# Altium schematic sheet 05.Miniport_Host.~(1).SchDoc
size A4; CheckedBy: <审核日期>; Author: 黄雄波; CompanyName: 广州周立功单片机科技有限公司; DocumentNumber: 5; SheetNumber: 5; SheetTotal: 7; PageSetup: Record=PageOptions¦CenterHorizontal=True¦CenterVertical=True¦PrintScale=1.00¦XCorrection=1.00¦YCorrection=1.00¦PrintKind=0¦BorderSize=5000000¦LeftOffset=0¦BottomOffset=0¦Orientation=2¦PaperLength=1000¦PaperWidth=1000¦Scale=100¦PaperSource=7¦PrintQuality=600¦MediaType=1¦DitherType=10¦PaperKind=A4¦PrintScaleMode=1; DesignDate: 2016-12-27; CheckDate: <审核人员>; SheetName: MiniPort接口; SheetVersion: V1.01; SheetDescription: MiniPort接口; productModel: AM116-Core; productName: 开发套件
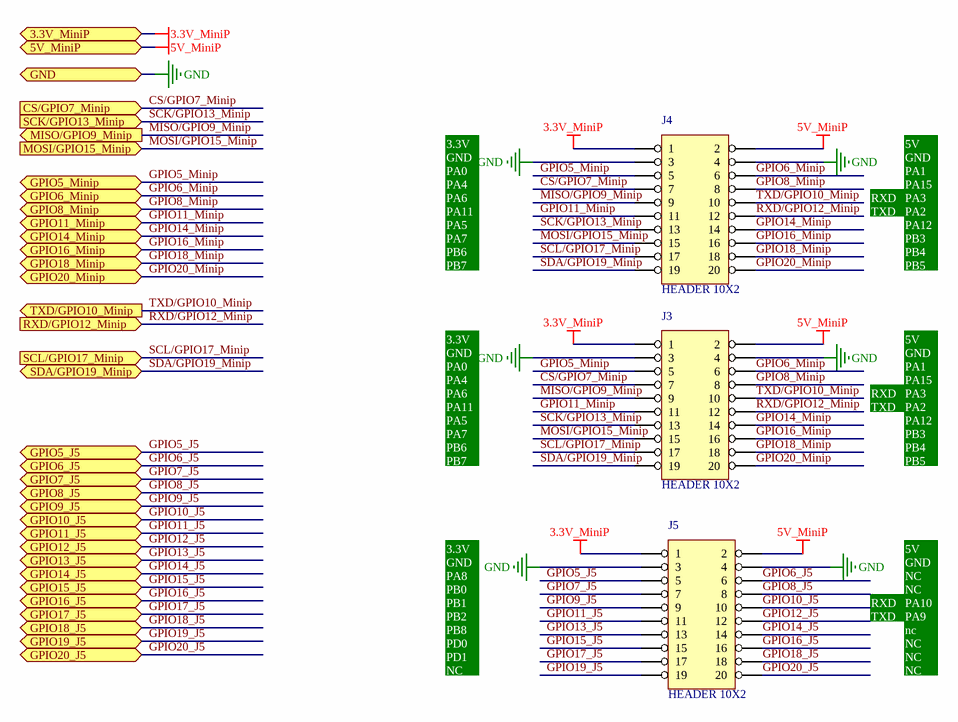
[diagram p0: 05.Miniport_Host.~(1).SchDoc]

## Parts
J3  HEADER 10X2  [IDC-20-2.54-R90]
J4  HEADER 10X2  [IDC-20-2.54-R90]
J5  HEADER 10X2  [IDC-20-2.54-R90]

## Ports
3.3V_MiniP, 5V_MiniP, CS/GPIO7_Minip (in), GND, GPIO5_J5 (bidir), GPIO5_Minip (bidir), GPIO6_J5 (bidir), GPIO6_Minip (bidir), GPIO7_J5 (bidir), GPIO8_J5 (bidir), GPIO8_Minip (bidir), GPIO9_J5 (bidir), GPIO10_J5 (bidir), GPIO11_J5 (bidir), GPIO11_Minip (bidir), GPIO12_J5 (bidir), GPIO13_J5 (bidir), GPIO14_J5 (bidir), GPIO14_Minip (bidir), GPIO15_J5 (bidir), GPIO16_J5 (bidir), GPIO16_Minip (bidir), GPIO17_J5 (bidir), GPIO18_J5 (bidir), GPIO18_Minip (bidir), GPIO19_J5 (bidir), GPIO20_J5 (bidir), GPIO20_Minip (bidir), MISO/GPIO9_Minip (out), MOSI/GPIO15_Minip (in), RXD/GPIO12_Minip (in), SCK/GPIO13_Minip (in), SCL/GPIO17_Minip (in), SDA/GPIO19_Minip (bidir), TXD/GPIO10_Minip (out)

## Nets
3.3V_MiniP: J3.1 J4.1 J5.1 ; port 3.3V_MiniP
5V_MiniP: J3.2 J4.2 J5.2 ; port 5V_MiniP
GND: J3.3 J3.4 J4.3 J4.4 J5.3 J5.4 ; port GND
CS/GPIO7_Minip: J3.7 J4.7 ; port CS/GPIO7_Minip
GPIO5_J5: J5.5 ; port GPIO5_J5
GPIO5_Minip: J3.5 J4.5 ; port GPIO5_Minip
GPIO6_J5: J5.6 ; port GPIO6_J5
GPIO6_Minip: J3.6 J4.6 ; port GPIO6_Minip
GPIO7_J5: J5.7 ; port GPIO7_J5
GPIO8_J5: J5.8 ; port GPIO8_J5
GPIO8_Minip: J3.8 J4.8 ; port GPIO8_Minip
GPIO9_J5: J5.9 ; port GPIO9_J5
GPIO10_J5: J5.10 ; port GPIO10_J5
GPIO11_J5: J5.11 ; port GPIO11_J5
GPIO11_Minip: J3.11 J4.11 ; port GPIO11_Minip
GPIO12_J5: J5.12 ; port GPIO12_J5
GPIO13_J5: J5.13 ; port GPIO13_J5
GPIO14_J5: J5.14 ; port GPIO14_J5
GPIO14_Minip: J3.14 J4.14 ; port GPIO14_Minip
GPIO15_J5: J5.15 ; port GPIO15_J5
GPIO16_J5: J5.16 ; port GPIO16_J5
GPIO16_Minip: J3.16 J4.16 ; port GPIO16_Minip
GPIO17_J5: J5.17 ; port GPIO17_J5
GPIO18_J5: J5.18 ; port GPIO18_J5
GPIO18_Minip: J3.18 J4.18 ; port GPIO18_Minip
GPIO19_J5: J5.19 ; port GPIO19_J5
GPIO20_J5: J5.20 ; port GPIO20_J5
GPIO20_Minip: J3.20 J4.20 ; port GPIO20_Minip
MISO/GPIO9_Minip: J3.9 J4.9 ; port MISO/GPIO9_Minip
MOSI/GPIO15_Minip: J3.15 J4.15 ; port MOSI/GPIO15_Minip
RXD/GPIO12_Minip: J3.12 J4.12 ; port RXD/GPIO12_Minip
SCK/GPIO13_Minip: J3.13 J4.13 ; port SCK/GPIO13_Minip
SCL/GPIO17_Minip: J3.17 J4.17 ; port SCL/GPIO17_Minip
SDA/GPIO19_Minip: J3.19 J4.19 ; port SDA/GPIO19_Minip
TXD/GPIO10_Minip: J3.10 J4.10 ; port TXD/GPIO10_Minip

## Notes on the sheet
- 3.3V
  GND
  PA0
  PA4
  PA6
  PA11
  PA5
  PA7
  PB6
  PB7
- TXD
- RXD
- 5V
  GND
  PA1
  PA15
  PA3
  PA2
  PA12
  PB3
  PB4
  PB5
- 3.3V
  GND
  PA8
  PB0
  PB1
  PB2
  PB8
  PD0
  PD1
  NC
- 5V
  GND
  NC
  NC
  PA10
  PA9
  nc
  NC
  NC
  NC

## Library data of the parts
J5 = HEADER 10X2: 物料代码: 1.10.11.0076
